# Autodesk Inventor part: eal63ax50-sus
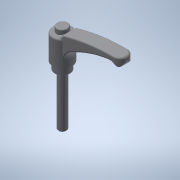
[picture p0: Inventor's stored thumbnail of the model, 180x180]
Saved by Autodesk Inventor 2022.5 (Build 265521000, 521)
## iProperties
Created: 2016-12
Part Number: eal63ax50-sus
Material: 一般
Document SubType Name: Modeling
Designer: imaocorp
Density: 1 g/cm^3
Appearance: 既定
Author: imaocorp
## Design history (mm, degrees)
node "eal63ax50-sus.x_t1"
node "eal63ax50-sus"
node "Base1"
